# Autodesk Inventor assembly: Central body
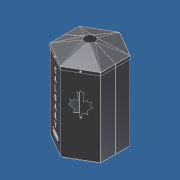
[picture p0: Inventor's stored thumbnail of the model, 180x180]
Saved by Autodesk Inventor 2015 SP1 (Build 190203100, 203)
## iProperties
Category: Mechanical Engineering Drawing and Design - CADD
Manager: Fábio Ricardo de Oliveira Souza
Company: SENAI - Serviço Nacional de Aprendizagem Industrial
Created: 2011-06
Part Number: Central body
Document SubType Name: Weldment
Designer: Guilherme Augusto Franco de Souza
Engineer: George Geraldo de Oliveia Silva
Authority: Fábio Ricardo de Oliveira Soza
Description: Sub-assembly
Weld Material: Welded Stainless Steel, 440C
Subject: WorldSkill 2011 - London, England
Author: Guilherme Augusto Franco de Souza
Revision Number: 00
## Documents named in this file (4)
- E:\Visitor Experience Project\WSI2015 - Visitor Experience Project\#46- Sheet Metal Technology\01- 3D Models\Outodoor Heater\2- Assemblies\Central body.iam
- E:\Visitor Experience Project\WSI2015 - Visitor Experience Project\#46- Sheet Metal Technology\01- 3D Models\Outodoor Heater\1- Parts\Central body - Half skirt.ipt
- E:\Visitor Experience Project\WSI2015 - Visitor Experience Project\#46- Sheet Metal Technology\01- 3D Models\Outodoor Heater\2- Assemblies\Bolted Connection.iam
- E:\Visitor Experience Project\WSI2015 - Visitor Experience Project\#46- Sheet Metal Technology\01- 3D Models\Outodoor Heater\2- Assemblies\Central body - Hex Cover.iam
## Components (7 placed, 3 different names)
1. Central body - Half skirt:1 — Mate:1, Flush:1, Mate:2
2. Central body - Half skirt:2 — Mate:1, Flush:1, Mate:2
3. Bolted Connection:1 [sub-assembly]
4. Bolted Connection:2 [sub-assembly]
5. Bolted Connection:3 [sub-assembly]
6. Bolted Connection:4 [sub-assembly]
7. Central body - Hex Cover:1 [sub-assembly]
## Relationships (3: Mate 2, Flush 1)
- Mate:1: Central body - Half skirt:1 ↔ Central body - Half skirt:2
- Flush:1: Central body - Half skirt:1 ↔ Central body - Half skirt:2
- Mate:2: Central body - Half skirt:1 ↔ Central body - Half skirt:2
